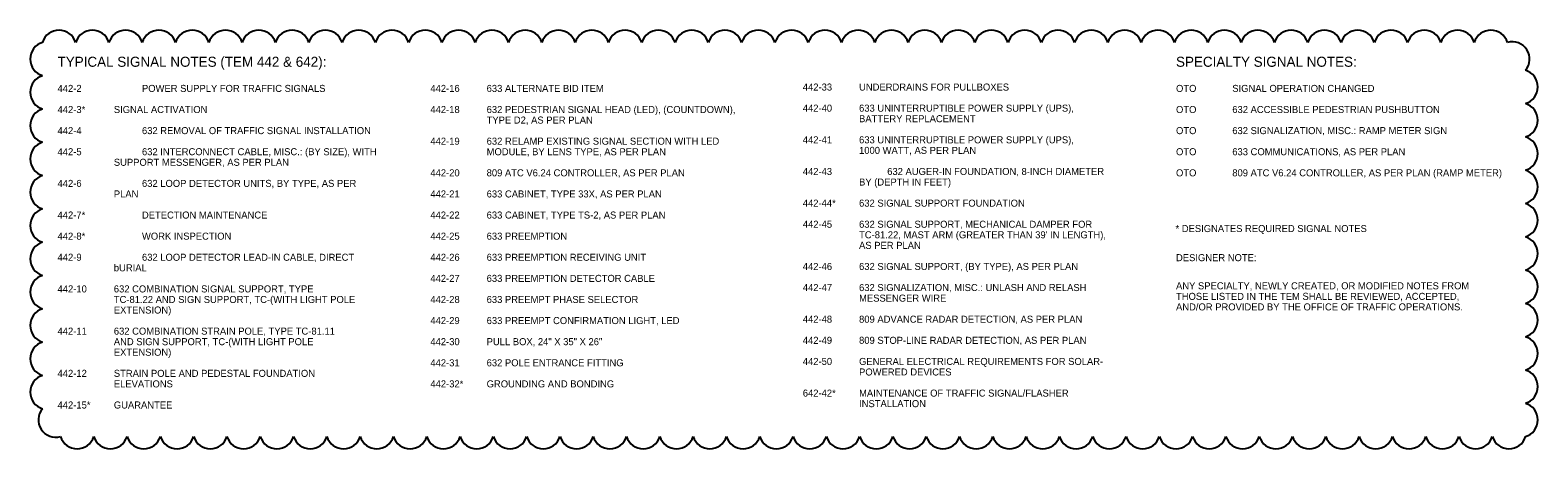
# Model space of a CAD drawing. Extents: x -18.7 to 62.3, y -3.1 to 33.6.
# Drawn here: x 3.2 to 33.21, y 25.22 to 33.55 of the extents above; entities that cross this region are included whole.
import ezdxf

# ---------------------------------------------------------------- set-up
doc = ezdxf.new("R2010")
doc.units = 0
doc.layers.add('SC_Scratch1', color=7, linetype='Continuous')

msp = doc.modelspace()

# ---------------------------------------------------------------- linework, layer by layer
at = {"layer": 'SC_Scratch1'}
for centre, start, end in [((3.779, 33.203), 17.5, 162.5), ((4.442, 33.203), 17.5, 162.5), ((5.104, 33.203), 17.5, 162.5), ((5.767, 33.203), 17.5, 162.5), ((6.43, 33.203), 17.5, 162.5), ((7.093, 33.203), 17.5, 162.5), ((7.755, 33.203), 17.5, 162.5), ((8.418, 33.203), 17.5, 162.5), ((9.081, 33.203), 17.5, 162.5), ((9.744, 33.203), 17.5, 162.5), ((10.406, 33.203), 17.5, 162.5), ((11.069, 33.203), 17.5, 162.5), ((11.732, 33.203), 17.5, 162.5), ((12.394, 33.203), 17.5, 162.5), ((13.057, 33.203), 17.5, 162.5), ((13.72, 33.203), 17.5, 162.5), ((14.383, 33.203), 17.5, 162.5), ((15.045, 33.203), 17.5, 162.5), ((15.708, 33.203), 17.5, 162.5), ((16.371, 33.203), 17.5, 162.5), ((17.033, 33.203), 17.5, 162.5), ((17.696, 33.203), 17.5, 162.5), ((18.359, 33.203), 17.5, 162.5), ((19.022, 33.203), 17.5, 162.5), ((19.684, 33.203), 17.5, 162.5), ((20.347, 33.203), 17.5, 162.5), ((21.01, 33.203), 17.5, 162.5), ((21.673, 33.203), 17.5, 162.5), ((22.335, 33.203), 17.5, 162.5), ((22.998, 33.203), 17.5, 162.5), ((23.661, 33.203), 17.5, 162.5), ((24.323, 33.203), 17.5, 162.5), ((24.986, 33.203), 17.5, 162.5), ((25.649, 33.203), 17.5, 162.5), ((26.312, 33.203), 17.5, 162.5), ((26.974, 33.203), 17.5, 162.5), ((27.637, 33.203), 17.5, 162.5), ((28.3, 33.203), 17.5, 162.5), ((28.963, 33.203), 17.5, 162.5), ((29.625, 33.203), 17.5, 162.5), ((30.288, 33.203), 17.5, 162.5), ((30.951, 33.203), 17.5, 162.5), ((31.613, 33.203), 17.5, 162.5), ((32.276, 33.203), 17.5, 162.5), ((32.7, 32.972), 320.4948, 105.4948), ((3.552, 32.976), 107.5, 252.5), ((32.864, 32.42), 287.5, 72.5), ((3.552, 32.313), 107.5, 252.5), ((3.552, 31.65), 107.5, 252.5), ((32.864, 31.757), 287.5, 72.5), ((3.552, 30.988), 107.5, 252.5), ((32.864, 31.095), 287.5, 72.5), ((3.552, 30.325), 107.5, 252.5), ((32.864, 30.432), 287.5, 72.5), ((32.864, 29.769), 287.5, 72.5), ((3.552, 29.662), 107.5, 252.5), ((32.864, 29.106), 287.5, 72.5), ((3.552, 28.999), 107.5, 252.5), ((3.552, 28.337), 107.5, 252.5), ((32.864, 28.444), 287.5, 72.5), ((3.552, 27.674), 107.5, 252.5), ((32.864, 27.781), 287.5, 72.5), ((3.552, 27.011), 107.5, 252.5), ((32.864, 27.118), 287.5, 72.5), ((32.864, 26.456), 287.5, 72.5), ((3.552, 26.348), 107.5, 252.5), ((32.864, 25.793), 287.5, 72.5), ((3.716, 25.796), 140.4948, 285.4948), ((4.14, 25.566), 197.5, 342.5), ((4.802, 25.566), 197.5, 342.5), ((5.465, 25.566), 197.5, 342.5), ((6.128, 25.566), 197.5, 342.5), ((6.791, 25.566), 197.5, 342.5), ((7.453, 25.566), 197.5, 342.5), ((8.116, 25.566), 197.5, 342.5), ((8.779, 25.566), 197.5, 342.5), ((9.442, 25.566), 197.5, 342.5), ((10.104, 25.566), 197.5, 342.5), ((10.767, 25.566), 197.5, 342.5), ((11.43, 25.566), 197.5, 342.5), ((12.092, 25.566), 197.5, 342.5), ((12.755, 25.566), 197.5, 342.5), ((13.418, 25.566), 197.5, 342.5), ((14.081, 25.566), 197.5, 342.5), ((14.743, 25.566), 197.5, 342.5), ((15.406, 25.566), 197.5, 342.5), ((16.069, 25.566), 197.5, 342.5), ((16.732, 25.566), 197.5, 342.5), ((17.394, 25.566), 197.5, 342.5), ((18.057, 25.566), 197.5, 342.5), ((18.72, 25.566), 197.5, 342.5), ((19.382, 25.566), 197.5, 342.5), ((20.045, 25.566), 197.5, 342.5), ((20.708, 25.566), 197.5, 342.5), ((21.371, 25.566), 197.5, 342.5), ((22.033, 25.566), 197.5, 342.5), ((22.696, 25.566), 197.5, 342.5), ((23.359, 25.566), 197.5, 342.5), ((24.021, 25.566), 197.5, 342.5), ((24.684, 25.566), 197.5, 342.5), ((25.347, 25.566), 197.5, 342.5), ((26.01, 25.566), 197.5, 342.5), ((26.672, 25.566), 197.5, 342.5), ((27.335, 25.566), 197.5, 342.5), ((27.998, 25.566), 197.5, 342.5), ((28.661, 25.566), 197.5, 342.5), ((29.323, 25.566), 197.5, 342.5), ((29.986, 25.566), 197.5, 342.5), ((30.649, 25.566), 197.5, 342.5), ((31.311, 25.566), 197.5, 342.5), ((31.974, 25.566), 197.5, 342.5), ((32.637, 25.566), 197.5, 342.5)]:
    msp.add_arc(centre, 0.347, start, end, dxfattribs=at)

# ---------------------------------------------------------------- texts
for s, height, p in [('TYPICAL SIGNAL NOTES (TEM 442 & 642):', 0.2, (3.75, 32.821)), ('SPECIALTY SIGNAL NOTES:', 0.2, (26.01, 32.821)), ('442-2', 0.14, (3.75, 32.321)), ('POWER SUPPLY FOR TRAFFIC SIGNALS ', 0.14, (5.43, 32.321)), ('442-16 ', 0.14, (11.17, 32.321)), ('633 ALTERNATE BID ITEM', 0.14, (12.29, 32.321)), ('442-33 ', 0.14, (18.582, 32.348)), ('UNDERDRAINS FOR PULLBOXES', 0.14, (19.702, 32.348)), ('OTO', 0.14, (26.01, 32.321)), ('SIGNAL OPERATION CHANGED', 0.14, (27.13, 32.321)), ('442-3* ', 0.14, (3.75, 31.901)), ('SIGNAL ACTIVATION', 0.14, (4.87, 31.901)), ('442-18 ', 0.14, (11.17, 31.901)), ('TYPE D2, AS PER PLAN', 0.14, (12.29, 31.691)), ('632 PEDESTRIAN SIGNAL HEAD (LED), (COUNTDOWN), ', 0.14, (12.29, 31.901)), ('442-40 ', 0.14, (18.582, 31.928)), ('633 UNINTERRUPTIBLE POWER SUPPLY (UPS), ', 0.14, (19.702, 31.928)), ('BATTERY REPLACEMENT', 0.14, (19.702, 31.718)), ('OTO', 0.14, (26.01, 31.901)), ('632 ACCESSIBLE PEDESTRIAN PUSHBUTTON', 0.14, (27.13, 31.901)), ('442-4', 0.14, (3.75, 31.481)), ('632 REMOVAL OF TRAFFIC SIGNAL INSTALLATION', 0.14, (5.43, 31.481)), ('OTO', 0.14, (26.01, 31.481)), ('632 SIGNALIZATION, MISC.: RAMP METER SIGN', 0.14, (27.13, 31.481)), ('632 INTERCONNECT CABLE, MISC.: (BY SIZE), WITH ', 0.14, (5.43, 31.061)), ('442-19 ', 0.14, (11.17, 31.271)), ('632 RELAMP EXISTING SIGNAL SECTION WITH LED ', 0.14, (12.29, 31.271)), ('442-41 ', 0.14, (18.582, 31.298)), ('633 UNINTERRUPTIBLE POWER SUPPLY (UPS), ', 0.14, (19.702, 31.298)), ('1000 WATT, AS PER PLAN', 0.14, (19.702, 31.088)), ('442-5', 0.14, (3.75, 31.061)), ('SUPPORT MESSENGER, AS PER PLAN', 0.14, (4.87, 30.851)), ('MODULE, BY LENS TYPE, AS PER PLAN', 0.14, (12.29, 31.061)), ('OTO', 0.14, (26.01, 31.061)), ('633 COMMUNICATIONS, AS PER PLAN', 0.14, (27.13, 31.061)), ('442-20 ', 0.14, (11.17, 30.641)), ('809 ATC V6.24 CONTROLLER, AS PER PLAN', 0.14, (12.29, 30.641)), ('442-43', 0.14, (18.582, 30.668)), ('632 AUGER-IN FOUNDATION, 8-INCH DIAMETER', 0.14, (20.262, 30.668)), ('OTO', 0.14, (26.01, 30.641)), ('809 ATC V6.24 CONTROLLER, AS PER PLAN (RAMP METER)', 0.14, (27.13, 30.641)), ('442-6', 0.14, (3.75, 30.431)), ('PLAN', 0.14, (4.87, 30.221)), ('632 LOOP DETECTOR UNITS, BY TYPE, AS PER ', 0.14, (5.43, 30.431)), ('442-21 ', 0.14, (11.17, 30.221)), ('633 CABINET, TYPE 33X, AS PER PLAN', 0.14, (12.29, 30.221)), ('BY (DEPTH IN FEET)', 0.14, (19.702, 30.458)), ('442-44* ', 0.14, (18.582, 30.038)), ('632 SIGNAL SUPPORT FOUNDATION', 0.14, (19.702, 30.038)), ('442-7*', 0.14, (3.75, 29.801)), ('DETECTION MAINTENANCE', 0.14, (5.43, 29.801)), ('442-22 ', 0.14, (11.17, 29.801)), ('633 CABINET, TYPE TS-2, AS PER PLAN', 0.14, (12.29, 29.801)), ('442-45 ', 0.14, (18.582, 29.618)), ('632 SIGNAL SUPPORT, MECHANICAL DAMPER FOR ', 0.14, (19.702, 29.618)), ('442-8*', 0.14, (3.75, 29.381)), ('WORK INSPECTION', 0.14, (5.43, 29.381)), ('442-25 ', 0.14, (11.17, 29.381)), ('633 PREEMPTION', 0.14, (12.29, 29.381)), ("TC-81.22, MAST ARM (GREATER THAN 39' IN LENGTH), ", 0.14, (19.702, 29.408)), ('* DESIGNATES REQUIRED SIGNAL NOTES', 0.14, (26, 29.532)), ('AS PER PLAN ', 0.14, (19.702, 29.198)), ('442-9', 0.14, (3.75, 28.961)), ('bURIAL', 0.14, (4.87, 28.751)), ('632 LOOP DETECTOR LEAD-IN CABLE, DIRECT ', 0.14, (5.43, 28.961)), ('442-26 ', 0.14, (11.17, 28.961)), ('633 PREEMPTION RECEIVING UNIT', 0.14, (12.29, 28.961)), ('442-46 ', 0.14, (18.582, 28.778)), ('632 SIGNAL SUPPORT, (BY TYPE), AS PER PLAN', 0.14, (19.702, 28.778)), ('DESIGNER NOTE:', 0.14, (26.01, 28.953)), ('442-27 ', 0.14, (11.17, 28.541)), ('633 PREEMPTION DETECTOR CABLE', 0.14, (12.29, 28.541)), ('ANY SPECIALTY, NEWLY CREATED, OR MODIFIED NOTES FROM ', 0.14, (26.01, 28.393)), ('442-10 ', 0.14, (3.75, 28.331)), ('TC-81.22 AND SIGN SUPPORT, TC-(WITH LIGHT POLE ', 0.14, (4.87, 28.121)), ('632 COMBINATION SIGNAL SUPPORT, TYPE ', 0.14, (4.87, 28.331)), ('442-28 ', 0.14, (11.17, 28.121)), ('633 PREEMPT PHASE SELECTOR', 0.14, (12.29, 28.121)), ('442-47 ', 0.14, (18.582, 28.358)), ('632 SIGNALIZATION, MISC.: UNLASH AND RELASH ', 0.14, (19.702, 28.358)), ('MESSENGER WIRE', 0.14, (19.702, 28.148)), ('THOSE LISTED IN THE TEM SHALL BE REVIEWED, ACCEPTED, ', 0.14, (26.01, 28.183)), ('EXTENSION)', 0.14, (4.87, 27.911)), ('AND/OR PROVIDED BY THE OFFICE OF TRAFFIC OPERATIONS.', 0.14, (26.01, 27.973)), ('442-11 ', 0.14, (3.75, 27.491)), ('632 COMBINATION STRAIN POLE, TYPE TC-81.11 ', 0.14, (4.87, 27.491)), ('442-29 ', 0.14, (11.17, 27.701)), ('633 PREEMPT CONFIRMATION LIGHT, LED', 0.14, (12.29, 27.701)), ('442-48 ', 0.14, (18.582, 27.728)), ('809 ADVANCE RADAR DETECTION, AS PER PLAN', 0.14, (19.702, 27.728)), ('AND SIGN SUPPORT, TC-(WITH LIGHT POLE ', 0.14, (4.87, 27.281)), ('442-30 ', 0.14, (11.17, 27.281)), ('PULL BOX, 24" X 35" X 26"', 0.14, (12.29, 27.281)), ('442-49 ', 0.14, (18.582, 27.308)), ('809 STOP-LINE RADAR DETECTION, AS PER PLAN', 0.14, (19.702, 27.308)), ('EXTENSION)', 0.14, (4.87, 27.071)), ('442-50 ', 0.14, (18.582, 26.888)), ('GENERAL ELECTRICAL REQUIREMENTS FOR SOLAR-', 0.14, (19.702, 26.888)), ('442-12 ', 0.14, (3.75, 26.651)), ('STRAIN POLE AND PEDESTAL FOUNDATION ', 0.14, (4.87, 26.651)), ('442-31 ', 0.14, (11.17, 26.861)), ('632 POLE ENTRANCE FITTING', 0.14, (12.29, 26.861)), ('POWERED DEVICES', 0.14, (19.702, 26.678)), ('ELEVATIONS', 0.14, (4.87, 26.441)), ('442-32*', 0.14, (11.17, 26.441)), ('GROUNDING AND BONDING', 0.14, (12.29, 26.441)), ('MAINTENANCE OF TRAFFIC SIGNAL/FLASHER', 0.14, (19.702, 26.258)), ('442-15*', 0.14, (3.75, 26.021)), ('GUARANTEE', 0.14, (4.87, 26.021)), ('642-42* ', 0.14, (18.582, 26.258)), ('INSTALLATION', 0.14, (19.702, 26.048))]:
    msp.add_text(s, height=height, dxfattribs=at).set_placement(p)

doc.saveas('drawing.dxf')
